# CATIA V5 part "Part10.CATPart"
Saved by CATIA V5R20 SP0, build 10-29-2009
Part number: 1bola238
Revision: ANY
Definition: UNKNOWN
Nomenclature: 1bola238
Source: Unknown
Bounding box of the stored display mesh (mm): x -1.19 to 1.19, y -1.19 to 1.19, z -1.19 to 1.19
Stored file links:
  C:\Users\Utente\Desktop\IO LAVORO\3D X SITO CF\CUMSA\3D files BE\BE 051317\Part10.CATPart
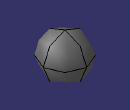
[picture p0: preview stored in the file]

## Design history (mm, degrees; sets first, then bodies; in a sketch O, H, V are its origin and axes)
Body1 "Revolución1" (main body)
  Solid1: solid without history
